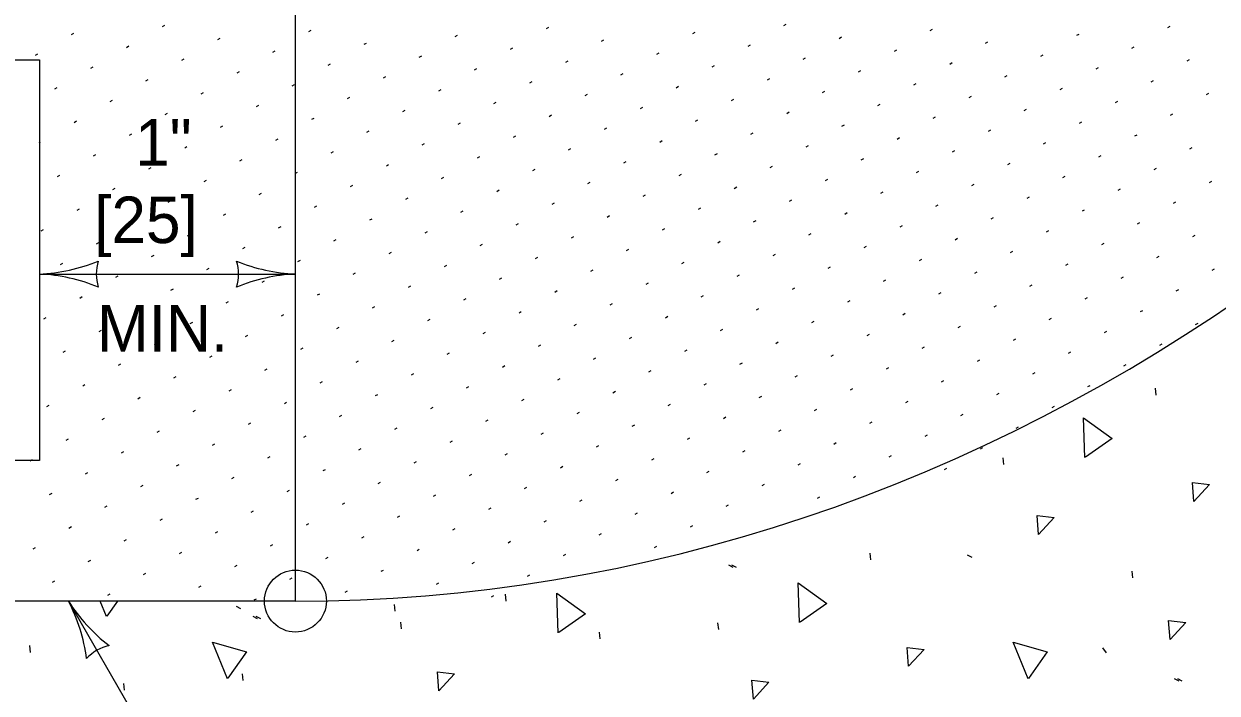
# Model space of a CAD drawing. Extents: x 49991.4 to 50021, y 49987.6 to 50011.4.
# Drawn here: x 50011.101 to 50012.641, y 49993.167 to 49994.031 of the extents above; entities that cross this region are included whole.
import ezdxf

# ---------------------------------------------------------------- set-up
doc = ezdxf.new("R2010")
doc.units = 0
for name, color, linetype in [('Level 1', 7, 'Continuous'), ('Level 15', 7, 'Continuous'), ('Level 2', 7, 'Continuous'), ('Level 3', 7, 'Continuous'), ('Level 4', 7, 'Continuous')]:
    doc.layers.add(name, color=color, linetype=linetype)

msp = doc.modelspace()

# ---------------------------------------------------------------- linework, layer by layer
at = {"layer": 'Level 1'}
for p, q in [((50010.6323, 49993.984), (50011.1207, 49993.984)), ((50011.1207, 49993.984), (50011.1207, 49993.4673)), ((50011.1207, 49993.4673), (50010.6333, 49993.4673)), ((50011.4513, 49993.2857), (50004.6259, 49993.2857))]:
    msp.add_line(p, q, dxfattribs=at)
msp.add_ellipse((50011.4513, 49996.2377), major_axis=(0, -2.952), ratio=0.83118, start_param=0, end_param=1.074783, dxfattribs=at)
at = {"layer": 'Level 15'}
msp.add_circle((50011.4513, 49993.2857), 0.04, dxfattribs=at)
at = {"layer": 'Level 3'}
for p, q in [((50011.4514, 49993.2857), (50011.4512, 49994.8936)), ((50011.2796, 49994.0271), (50011.2827, 49994.0288)), ((50011.7753, 49994.0246), (50011.7784, 49994.0264)), ((50012.082, 49994.0285), (50012.0851, 49994.0302)), ((50012.5777, 49994.026), (50012.5808, 49994.0277)), ((50011.162, 49994.0169), (50011.165, 49994.0186)), ((50011.351, 49994.0105), (50011.354, 49994.0123)), ((50011.4687, 49994.0207), (50011.4717, 49994.0225)), ((50011.6577, 49994.0144), (50011.6607, 49994.0161)), ((50011.8467, 49994.0081), (50011.8497, 49994.0098)), ((50011.9644, 49994.0183), (50011.9674, 49994.02)), ((50012.1534, 49994.0119), (50012.1564, 49994.0137)), ((50012.2711, 49994.0221), (50012.2741, 49994.0239)), ((50012.4601, 49994.0158), (50012.4631, 49994.0175)), ((50011.2333, 49994.0003), (50011.2363, 49994.0021)), ((50011.4223, 49993.994), (50011.4253, 49993.9957)), ((50011.54, 49994.0042), (50011.543, 49994.0059)), ((50011.729, 49993.9978), (50011.732, 49993.9996)), ((50012.0357, 49994.0017), (50012.0387, 49994.0035)), ((50012.2247, 49993.9954), (50012.2277, 49993.9971)), ((50012.3424, 49994.0056), (50012.3454, 49994.0073)), ((50012.5314, 49993.9992), (50012.5344, 49994.001)), ((50011.1156, 49993.9901), (50011.1187, 49993.9919)), ((50011.3046, 49993.9838), (50011.3077, 49993.9855)), ((50011.4937, 49993.9774), (50011.4967, 49993.9792)), ((50011.6113, 49993.9876), (50011.6144, 49993.9894)), ((50011.8003, 49993.9813), (50011.8034, 49993.983)), ((50011.918, 49993.9915), (50011.9211, 49993.9933)), ((50012.107, 49993.9852), (50012.1101, 49993.9869)), ((50012.2961, 49993.9788), (50012.2991, 49993.9806)), ((50012.4137, 49993.989), (50012.4168, 49993.9908)), ((50012.6027, 49993.9827), (50012.6058, 49993.9844)), ((50011.187, 49993.9736), (50011.19, 49993.9753)), ((50011.376, 49993.9672), (50011.379, 49993.969)), ((50011.565, 49993.9609), (50011.568, 49993.9626)), ((50011.6827, 49993.9711), (50011.6857, 49993.9728)), ((50011.8717, 49993.9648), (50011.8747, 49993.9665)), ((50011.9894, 49993.975), (50011.9924, 49993.9767)), ((50012.1784, 49993.9686), (50012.1814, 49993.9704)), ((50012.3674, 49993.9623), (50012.3704, 49993.964)), ((50012.4851, 49993.9725), (50012.4881, 49993.9742)), ((50011.1406, 49993.9468), (50011.1437, 49993.9486)), ((50011.2583, 49993.957), (50011.2613, 49993.9588)), ((50011.4473, 49993.9507), (50011.4503, 49993.9524)), ((50011.754, 49993.9545), (50011.757, 49993.9563)), ((50011.943, 49993.9482), (50011.9461, 49993.95)), ((50012.0607, 49993.9584), (50012.0637, 49993.9602)), ((50012.2497, 49993.9521), (50012.2527, 49993.9538)), ((50012.4387, 49993.9457), (50012.4418, 49993.9475)), ((50012.5564, 49993.9559), (50012.5594, 49993.9577)), ((50011.212, 49993.9303), (50011.215, 49993.932)), ((50011.3296, 49993.9405), (50011.3327, 49993.9422)), ((50011.5187, 49993.9341), (50011.5217, 49993.9359)), ((50011.6363, 49993.9443), (50011.6394, 49993.9461)), ((50011.8253, 49993.938), (50011.8284, 49993.9397)), ((50012.0144, 49993.9317), (50012.0174, 49993.9334)), ((50012.132, 49993.9419), (50012.1351, 49993.9436)), ((50012.3211, 49993.9355), (50012.3241, 49993.9373)), ((50012.6277, 49993.9394), (50012.6308, 49993.9411)), ((50011.401, 49993.9239), (50011.404, 49993.9257)), ((50011.59, 49993.9176), (50011.593, 49993.9193)), ((50011.7077, 49993.9278), (50011.7107, 49993.9295)), ((50011.8967, 49993.9215), (50011.8997, 49993.9232)), ((50012.0857, 49993.9151), (50012.0887, 49993.9169)), ((50012.2034, 49993.9253), (50012.2064, 49993.9271)), ((50012.3924, 49993.919), (50012.3954, 49993.9207)), ((50012.5101, 49993.9292), (50012.5131, 49993.9309)), ((50011.1656, 49993.9035), (50011.1687, 49993.9053)), ((50011.2833, 49993.9137), (50011.2863, 49993.9155)), ((50011.4723, 49993.9074), (50011.4753, 49993.9091)), ((50011.6613, 49993.901), (50011.6644, 49993.9028)), ((50011.779, 49993.9112), (50011.782, 49993.913)), ((50011.968, 49993.9049), (50011.9711, 49993.9067)), ((50012.2747, 49993.9088), (50012.2777, 49993.9105)), ((50012.4637, 49993.9024), (50012.4668, 49993.9042)), ((50012.5814, 49993.9126), (50012.5844, 49993.9144)), ((50011.237, 49993.887), (50011.24, 49993.8887)), ((50011.3546, 49993.8972), (50011.3577, 49993.8989)), ((50011.5437, 49993.8908), (50011.5467, 49993.8926)), ((50011.7327, 49993.8845), (50011.7357, 49993.8862)), ((50011.8503, 49993.8947), (50011.8534, 49993.8964)), ((50012.0394, 49993.8884), (50012.0424, 49993.8901)), ((50012.157, 49993.8986), (50012.1601, 49993.9003)), ((50012.3461, 49993.8922), (50012.3491, 49993.894)), ((50012.5351, 49993.8859), (50012.5381, 49993.8876)), ((50011.1205, 49993.8775), (50011.1223, 49993.8785)), ((50011.3083, 49993.8704), (50011.3113, 49993.8722)), ((50011.426, 49993.8806), (50011.429, 49993.8824)), ((50011.615, 49993.8743), (50011.618, 49993.876)), ((50011.9217, 49993.8781), (50011.9247, 49993.8799)), ((50012.1107, 49993.8718), (50012.1137, 49993.8736)), ((50012.2284, 49993.882), (50012.2314, 49993.8838)), ((50012.4174, 49993.8757), (50012.4204, 49993.8774)), ((50012.6064, 49993.8693), (50012.6094, 49993.8711)), ((50011.1906, 49993.8602), (50011.1937, 49993.862)), ((50011.3796, 49993.8539), (50011.3827, 49993.8556)), ((50011.4973, 49993.8641), (50011.5003, 49993.8658)), ((50011.6863, 49993.8577), (50011.6894, 49993.8595)), ((50011.804, 49993.8679), (50011.807, 49993.8697)), ((50011.993, 49993.8616), (50011.9961, 49993.8634)), ((50012.182, 49993.8553), (50012.1851, 49993.857)), ((50012.2997, 49993.8655), (50012.3027, 49993.8672)), ((50012.4887, 49993.8591), (50012.4918, 49993.8609)), ((50011.262, 49993.8437), (50011.265, 49993.8454)), ((50011.5687, 49993.8475), (50011.5717, 49993.8493)), ((50011.7577, 49993.8412), (50011.7607, 49993.8429)), ((50011.8753, 49993.8514), (50011.8784, 49993.8531)), ((50012.0644, 49993.8451), (50012.0674, 49993.8468)), ((50012.2534, 49993.8387), (50012.2564, 49993.8405)), ((50012.3711, 49993.8489), (50012.3741, 49993.8507)), ((50012.5601, 49993.8426), (50012.5631, 49993.8443)), ((50011.1443, 49993.8335), (50011.1473, 49993.8352)), ((50011.3333, 49993.8271), (50011.3363, 49993.8289)), ((50011.451, 49993.8373), (50011.454, 49993.8391)), ((50011.64, 49993.831), (50011.643, 49993.8327)), ((50011.829, 49993.8246), (50011.832, 49993.8264)), ((50011.9467, 49993.8348), (50011.9497, 49993.8366)), ((50012.1357, 49993.8285), (50012.1387, 49993.8303)), ((50012.3247, 49993.8222), (50012.3277, 49993.8239)), ((50012.4424, 49993.8324), (50012.4454, 49993.8341)), ((50012.6314, 49993.826), (50012.6344, 49993.8278)), ((50011.2156, 49993.8169), (50011.2187, 49993.8187)), ((50011.4046, 49993.8106), (50011.4077, 49993.8123)), ((50011.5223, 49993.8208), (50011.5253, 49993.8225)), ((50011.7113, 49993.8144), (50011.7144, 49993.8162)), ((50011.9003, 49993.8081), (50011.9034, 49993.8098)), ((50012.018, 49993.8183), (50012.0211, 49993.8201)), ((50012.207, 49993.812), (50012.2101, 49993.8137)), ((50012.5137, 49993.8158), (50012.5168, 49993.8176)), ((50011.287, 49993.8004), (50011.29, 49993.8021)), ((50011.476, 49993.794), (50011.479, 49993.7958)), ((50011.5937, 49993.8042), (50011.5967, 49993.806)), ((50011.7827, 49993.7979), (50011.7857, 49993.7996)), ((50011.9717, 49993.7915), (50011.9747, 49993.7933)), ((50012.0894, 49993.8018), (50012.0924, 49993.8035)), ((50012.2784, 49993.7954), (50012.2814, 49993.7972)), ((50012.3961, 49993.8056), (50012.3991, 49993.8074)), ((50012.5851, 49993.7993), (50012.5881, 49993.801)), ((50011.1693, 49993.7902), (50011.1723, 49993.7919)), ((50011.3583, 49993.7838), (50011.3613, 49993.7856)), ((50011.5473, 49993.7775), (50011.5503, 49993.7792)), ((50011.665, 49993.7877), (50011.668, 49993.7894)), ((50011.854, 49993.7813), (50011.857, 49993.7831)), ((50012.1607, 49993.7852), (50012.1637, 49993.787)), ((50012.3497, 49993.7789), (50012.3527, 49993.7806)), ((50012.4674, 49993.7891), (50012.4704, 49993.7908)), ((50011.1229, 49993.7634), (50011.126, 49993.7652)), ((50011.2406, 49993.7736), (50011.2437, 49993.7754)), ((50011.4296, 49993.7673), (50011.4327, 49993.769)), ((50011.6187, 49993.7609), (50011.6217, 49993.7627)), ((50011.7363, 49993.7711), (50011.7394, 49993.7729)), ((50011.9253, 49993.7648), (50011.9284, 49993.7665)), ((50012.043, 49993.775), (50012.0461, 49993.7767)), ((50012.232, 49993.7687), (50012.2351, 49993.7704)), ((50012.4211, 49993.7623), (50012.4241, 49993.7641)), ((50012.5387, 49993.7725), (50012.5418, 49993.7743)), ((50011.1943, 49993.7469), (50011.1973, 49993.7486)), ((50011.312, 49993.7571), (50011.315, 49993.7588)), ((50011.501, 49993.7507), (50011.504, 49993.7525)), ((50011.8077, 49993.7546), (50011.8107, 49993.7563)), ((50011.9967, 49993.7482), (50011.9997, 49993.75)), ((50012.1144, 49993.7585), (50012.1174, 49993.7602)), ((50012.3034, 49993.7521), (50012.3064, 49993.7539)), ((50012.4924, 49993.7458), (50012.4954, 49993.7475)), ((50012.6101, 49993.756), (50012.6131, 49993.7577)), ((50011.2656, 49993.7303), (50011.2687, 49993.7321)), ((50011.3833, 49993.7405), (50011.3863, 49993.7423)), ((50011.5723, 49993.7342), (50011.5753, 49993.7359)), ((50011.69, 49993.7444), (50011.693, 49993.7461)), ((50011.879, 49993.738), (50011.882, 49993.7398)), ((50012.068, 49993.7317), (50012.0711, 49993.7334)), ((50012.1857, 49993.7419), (50012.1887, 49993.7437)), ((50012.3747, 49993.7356), (50012.3777, 49993.7373)), ((50011.1479, 49993.7201), (50011.151, 49993.7219)), ((50011.4546, 49993.724), (50011.4577, 49993.7257)), ((50011.6437, 49993.7176), (50011.6467, 49993.7194)), ((50011.7613, 49993.7278), (50011.7644, 49993.7296)), ((50011.9503, 49993.7215), (50011.9534, 49993.7232)), ((50012.1394, 49993.7152), (50012.1424, 49993.7169)), ((50012.257, 49993.7254), (50012.2601, 49993.7271)), ((50012.4461, 49993.719), (50012.4491, 49993.7208)), ((50012.5637, 49993.7292), (50012.5668, 49993.731)), ((50011.2193, 49993.7036), (50011.2223, 49993.7053)), ((50011.337, 49993.7138), (50011.34, 49993.7155)), ((50011.526, 49993.7074), (50011.529, 49993.7092)), ((50011.715, 49993.7011), (50011.718, 49993.7028)), ((50011.8327, 49993.7113), (50011.8357, 49993.713)), ((50012.0217, 49993.7049), (50012.0247, 49993.7067)), ((50012.3284, 49993.7088), (50012.3314, 49993.7106)), ((50012.5174, 49993.7025), (50012.5204, 49993.7042)), ((50012.6351, 49993.7127), (50012.6381, 49993.7144)), ((50011.2906, 49993.687), (50011.2937, 49993.6888)), ((50011.4083, 49993.6972), (50011.4113, 49993.699)), ((50011.5973, 49993.6909), (50011.6003, 49993.6926)), ((50011.7863, 49993.6845), (50011.7894, 49993.6863)), ((50011.904, 49993.6947), (50011.907, 49993.6965)), ((50012.093, 49993.6884), (50012.0961, 49993.6901)), ((50012.2107, 49993.6986), (50012.2137, 49993.7004)), ((50012.3997, 49993.6923), (50012.4027, 49993.694)), ((50012.5887, 49993.6859), (50012.5918, 49993.6877)), ((50011.1729, 49993.6768), (50011.176, 49993.6786)), ((50011.362, 49993.6705), (50011.365, 49993.6722)), ((50011.4796, 49993.6807), (50011.4827, 49993.6824)), ((50011.6687, 49993.6743), (50011.6717, 49993.6761)), ((50011.8577, 49993.668), (50011.8607, 49993.6697)), ((50011.9753, 49993.6782), (50011.9784, 49993.6799)), ((50012.1644, 49993.6718), (50012.1674, 49993.6736)), ((50012.282, 49993.6821), (50012.2851, 49993.6838)), ((50012.4711, 49993.6757), (50012.4741, 49993.6775)), ((50011.2443, 49993.6603), (50011.2473, 49993.662)), ((50011.4333, 49993.6539), (50011.4363, 49993.6557)), ((50011.551, 49993.6641), (50011.554, 49993.6659)), ((50011.74, 49993.6578), (50011.743, 49993.6595)), ((50012.0467, 49993.6616), (50012.0497, 49993.6634)), ((50012.2357, 49993.6553), (50012.2387, 49993.6571)), ((50012.3534, 49993.6655), (50012.3564, 49993.6673)), ((50012.5424, 49993.6592), (50012.5454, 49993.6609)), ((50011.1266, 49993.6501), (50011.1296, 49993.6518)), ((50011.3156, 49993.6437), (50011.3187, 49993.6455)), ((50011.5046, 49993.6374), (50011.5077, 49993.6391)), ((50011.6223, 49993.6476), (50011.6253, 49993.6493)), ((50011.8113, 49993.6412), (50011.8144, 49993.643)), ((50011.929, 49993.6514), (50011.932, 49993.6532)), ((50012.118, 49993.6451), (50012.1211, 49993.6468)), ((50012.307, 49993.6388), (50012.3101, 49993.6405)), ((50012.4247, 49993.649), (50012.4277, 49993.6507)), ((50012.6137, 49993.6426), (50012.6168, 49993.6444)), ((50011.1979, 49993.6335), (50011.201, 49993.6353)), ((50011.387, 49993.6272), (50011.39, 49993.6289)), ((50011.6937, 49993.631), (50011.6967, 49993.6328)), ((50011.8827, 49993.6247), (50011.8857, 49993.6264)), ((50012.0003, 49993.6349), (50012.0034, 49993.6366)), ((50012.1894, 49993.6285), (50012.1924, 49993.6303)), ((50012.3784, 49993.6222), (50012.3814, 49993.624)), ((50012.4961, 49993.6324), (50012.4991, 49993.6342)), ((50011.1516, 49993.6068), (50011.1546, 49993.6085)), ((50011.2693, 49993.617), (50011.2723, 49993.6187)), ((50011.4583, 49993.6106), (50011.4613, 49993.6124)), ((50011.576, 49993.6208), (50011.579, 49993.6226)), ((50011.765, 49993.6145), (50011.768, 49993.6162)), ((50011.954, 49993.6081), (50011.957, 49993.6099)), ((50012.0717, 49993.6183), (50012.0747, 49993.6201)), ((50012.2607, 49993.612), (50012.2637, 49993.6137)), ((50012.5674, 49993.6159), (50012.5704, 49993.6176)), ((50011.3406, 49993.6004), (50011.3437, 49993.6022)), ((50011.5296, 49993.5941), (50011.5327, 49993.5958)), ((50011.6473, 49993.6043), (50011.6503, 49993.606)), ((50011.8363, 49993.5979), (50011.8394, 49993.5997)), ((50012.0253, 49993.5916), (50012.0284, 49993.5933)), ((50012.143, 49993.6018), (50012.1461, 49993.6035)), ((50012.332, 49993.5955), (50012.3351, 49993.5972)), ((50012.4497, 49993.6057), (50012.4527, 49993.6074)), ((50011.2229, 49993.5902), (50011.226, 49993.592)), ((50011.412, 49993.5839), (50011.415, 49993.5856)), ((50011.601, 49993.5775), (50011.604, 49993.5793)), ((50011.7187, 49993.5877), (50011.7217, 49993.5895)), ((50011.9077, 49993.5814), (50011.9107, 49993.5831)), ((50012.2144, 49993.5852), (50012.2174, 49993.587)), ((50012.4034, 49993.5789), (50012.4064, 49993.5807)), ((50012.5211, 49993.5891), (50012.5241, 49993.5909)), ((50011.1766, 49993.5634), (50011.1796, 49993.5652)), ((50011.2943, 49993.5737), (50011.2973, 49993.5754)), ((50011.4833, 49993.5673), (50011.4863, 49993.5691)), ((50011.6723, 49993.561), (50011.6753, 49993.5627)), ((50011.79, 49993.5712), (50011.793, 49993.5729)), ((50011.979, 49993.5648), (50011.982, 49993.5666)), ((50012.0967, 49993.575), (50012.0997, 49993.5768)), ((50012.2857, 49993.5687), (50012.2887, 49993.5704)), ((50012.4747, 49993.5624), (50012.4777, 49993.5641)), ((50011.2479, 49993.5469), (50011.251, 49993.5487)), ((50011.3656, 49993.5571), (50011.3687, 49993.5589)), ((50011.5546, 49993.5508), (50011.5577, 49993.5525)), ((50011.8613, 49993.5546), (50011.8644, 49993.5564)), ((50012.0503, 49993.5483), (50012.0534, 49993.55)), ((50012.168, 49993.5585), (50012.1711, 49993.5602)), ((50012.357, 49993.5522), (50012.3601, 49993.5539)), ((50011.1303, 49993.5367), (50011.1333, 49993.5384)), ((50011.3193, 49993.5304), (50011.3223, 49993.5321)), ((50011.437, 49993.5406), (50011.44, 49993.5423)), ((50011.626, 49993.5342), (50011.629, 49993.536)), ((50011.7437, 49993.5444), (50011.7467, 49993.5462)), ((50011.9327, 49993.5381), (50011.9357, 49993.5398)), ((50012.1217, 49993.5317), (50012.1247, 49993.5335)), ((50012.2394, 49993.5419), (50012.2424, 49993.5437)), ((50012.4284, 49993.5356), (50012.4314, 49993.5374)), ((50011.2016, 49993.5201), (50011.2046, 49993.5219)), ((50011.5083, 49993.524), (50011.5113, 49993.5258)), ((50011.6973, 49993.5177), (50011.7003, 49993.5194)), ((50011.815, 49993.5279), (50011.818, 49993.5296)), ((50012.004, 49993.5215), (50012.007, 49993.5233)), ((50012.193, 49993.5152), (50012.1961, 49993.5169)), ((50012.3107, 49993.5254), (50012.3137, 49993.5271)), ((50011.2729, 49993.5036), (50011.276, 49993.5054)), ((50011.3906, 49993.5138), (50011.3937, 49993.5156)), ((50011.5796, 49993.5075), (50011.5827, 49993.5092)), ((50011.7687, 49993.5011), (50011.7717, 49993.5029)), ((50011.8863, 49993.5113), (50011.8894, 49993.5131)), ((50012.0753, 49993.505), (50012.0784, 49993.5067)), ((50012.2644, 49993.4986), (50012.2674, 49993.5004)), ((50012.382, 49993.5088), (50012.3851, 49993.5106)), ((50011.1553, 49993.4934), (50011.1583, 49993.4951)), ((50011.3443, 49993.4871), (50011.3473, 49993.4888)), ((50011.462, 49993.4973), (50011.465, 49993.499)), ((50011.651, 49993.4909), (50011.654, 49993.4927)), ((50011.84, 49993.4846), (50011.843, 49993.4863)), ((50011.9577, 49993.4948), (50011.9607, 49993.4965)), ((50012.1467, 49993.4884), (50012.1497, 49993.4902)), ((50011.2266, 49993.4768), (50011.2296, 49993.4786)), ((50011.4156, 49993.4705), (50011.4187, 49993.4723)), ((50011.5333, 49993.4807), (50011.5363, 49993.4825)), ((50011.7223, 49993.4744), (50011.7253, 49993.4761)), ((50011.9113, 49993.468), (50011.9144, 49993.4698)), ((50012.029, 49993.4782), (50012.032, 49993.48)), ((50012.218, 49993.4719), (50012.2211, 49993.4736)), ((50012.3357, 49993.4821), (50012.3387, 49993.4838)), ((50011.1089, 49993.4666), (50011.112, 49993.4684)), ((50011.2979, 49993.4603), (50011.301, 49993.462)), ((50011.487, 49993.454), (50011.49, 49993.4557)), ((50011.6046, 49993.4642), (50011.6077, 49993.4659)), ((50011.7937, 49993.4578), (50011.7967, 49993.4596)), ((50012.1003, 49993.4617), (50012.1034, 49993.4634)), ((50012.2894, 49993.4553), (50012.2924, 49993.4571)), ((50011.1803, 49993.4501), (50011.1833, 49993.4518)), ((50011.3693, 49993.4438), (50011.3723, 49993.4455)), ((50011.5583, 49993.4374), (50011.5613, 49993.4392)), ((50011.676, 49993.4476), (50011.679, 49993.4494)), ((50011.865, 49993.4413), (50011.868, 49993.443)), ((50011.9827, 49993.4515), (50011.9857, 49993.4532)), ((50012.1717, 49993.4451), (50012.1747, 49993.4469)), ((50011.1339, 49993.4233), (50011.137, 49993.4251)), ((50011.2516, 49993.4335), (50011.2546, 49993.4353)), ((50011.4406, 49993.4272), (50011.4437, 49993.429)), ((50011.7473, 49993.4311), (50011.7503, 49993.4328)), ((50011.9363, 49993.4247), (50011.9394, 49993.4265)), ((50012.054, 49993.4349), (50012.057, 49993.4367)), ((50011.2053, 49993.4068), (50011.2083, 49993.4085)), ((50011.3229, 49993.417), (50011.326, 49993.4187)), ((50011.512, 49993.4107), (50011.515, 49993.4124)), ((50011.6296, 49993.4209), (50011.6327, 49993.4226)), ((50011.8187, 49993.4145), (50011.8217, 49993.4163)), ((50012.0077, 49993.4082), (50012.0107, 49993.4099)), ((50012.1253, 49993.4184), (50012.1284, 49993.4201)), ((50011.3943, 49993.4005), (50011.3973, 49993.4022)), ((50011.5833, 49993.3941), (50011.5863, 49993.3959)), ((50011.701, 49993.4043), (50011.704, 49993.4061)), ((50011.89, 49993.398), (50011.893, 49993.3997)), ((50011.1589, 49993.38), (50011.162, 49993.3818)), ((50011.2766, 49993.3902), (50011.2796, 49993.392)), ((50011.4656, 49993.3839), (50011.4687, 49993.3857)), ((50011.6546, 49993.3776), (50011.6577, 49993.3793)), ((50011.7723, 49993.3878), (50011.7753, 49993.3895)), ((50011.9613, 49993.3814), (50011.9644, 49993.3832)), ((50011.2303, 49993.3635), (50011.2333, 49993.3652)), ((50011.3479, 49993.3737), (50011.351, 49993.3754)), ((50011.537, 49993.3674), (50011.54, 49993.3691)), ((50011.726, 49993.361), (50011.729, 49993.3628)), ((50011.8437, 49993.3712), (50011.8467, 49993.373)), ((50011.1126, 49993.3533), (50011.1156, 49993.355)), ((50011.3016, 49993.3469), (50011.3046, 49993.3487)), ((50011.4193, 49993.3571), (50011.4223, 49993.3589)), ((50011.6083, 49993.3508), (50011.6113, 49993.3526)), ((50011.7973, 49993.3445), (50011.8003, 49993.3462)), ((50011.915, 49993.3547), (50011.918, 49993.3564)), ((50011.1839, 49993.3367), (50011.187, 49993.3385)), ((50011.3729, 49993.3304), (50011.376, 49993.3321)), ((50011.4906, 49993.3406), (50011.4937, 49993.3424)), ((50011.6796, 49993.3343), (50011.6827, 49993.336)), ((50011.2553, 49993.3202), (50011.2583, 49993.3219)), ((50011.4443, 49993.3138), (50011.4473, 49993.3156)), ((50011.562, 49993.3241), (50011.565, 49993.3258)), ((50011.751, 49993.3177), (50011.754, 49993.3195)), ((50011.1376, 49993.31), (50011.1406, 49993.3117)), ((50011.3266, 49993.3036), (50011.3296, 49993.3054)), ((50011.6333, 49993.3075), (50011.6363, 49993.3093)), ((50011.1581, 49993.2857), (50011.7617, 49992.2404)), ((50011.2089, 49993.2934), (50011.212, 49993.2952)), ((50011.3979, 49993.2871), (50011.401, 49993.2888)), ((50011.5156, 49993.2973), (50011.5187, 49993.2991)), ((50011.7046, 49993.291), (50011.7077, 49993.2927))]:
    msp.add_line(p, q, dxfattribs=at)
msp.add_lwpolyline([(50011.1207, 49993.7077), (50011.3394, 49993.7077), (50011.4513, 49993.7077)], dxfattribs=at)
for centre, radius, start, end in [((50011.1092, 49993.9404), 0.233, 272.8273, 292.0772), ((50011.2489, 49993.7077), 0.0548, 162.1388, 197.8612), ((50011.4605, 49993.9298), 0.2223, 247.456, 267.6395), ((50011.3231, 49993.7077), 0.0548, 342.1388, 17.8612), ((50011.1116, 49993.4855), 0.2223, 67.456, 87.6395), ((50011.4628, 49993.475), 0.233, 92.8273, 112.0772), ((50010.9612, 49993.1826), 0.2223, 7.456, 27.6395), ((50011.3539, 49993.412), 0.233, 212.8273, 232.0772), ((50011.2222, 49993.1747), 0.0548, 102.1388, 137.8612)]:
    msp.add_arc(centre, radius, start, end, dxfattribs=at)
at = {"layer": 'Level 4'}
for p, q in [((50012.5626, 49993.5516), (50012.5617, 49993.5603)), ((50012.3662, 49993.4618), (50012.3653, 49993.4705)), ((50012.1942, 49993.3389), (50012.1933, 49993.3476)), ((50012.0103, 49993.3323), (50012.0161, 49993.3295)), ((50012.0144, 49993.3323), (50012.0202, 49993.3295)), ((50012.3187, 49993.3452), (50012.3245, 49993.3423)), ((50012.5326, 49993.3158), (50012.5316, 49993.3245)), ((50011.7235, 49993.2857), (50011.7226, 49993.2944)), ((50011.3746, 49993.279), (50011.3803, 49993.2762)), ((50011.58, 49993.2727), (50011.5791, 49993.2814)), ((50011.3961, 49993.2662), (50011.4019, 49993.2633)), ((50011.4002, 49993.2662), (50011.406, 49993.2634)), ((50011.5884, 49993.2497), (50011.5875, 49993.2584)), ((50011.9979, 49993.2491), (50011.9969, 49993.2578)), ((50011.845, 49993.2369), (50011.844, 49993.2456)), ((50011.1093, 49993.2195), (50011.1084, 49993.2282)), ((50012.4933, 49993.2253), (50012.498, 49993.2189)), ((50011.2308, 49993.1707), (50011.2299, 49993.1794)), ((50011.3837, 49993.183), (50011.3828, 49993.1917)), ((50012.5861, 49993.1858), (50012.5919, 49993.1829)), ((50012.5902, 49993.1858), (50012.5959, 49993.1829))]:
    msp.add_line(p, q, dxfattribs=at)
for points in [[(50012.4707, 49993.4709), (50012.4689, 49993.5221), (50012.5059, 49993.4953), (50012.4715, 49993.4713)], [(50012.6114, 49993.4141), (50012.6095, 49993.4387), (50012.6315, 49993.436), (50012.6114, 49993.4141)], [(50012.411, 49993.3718), (50012.4092, 49993.3963), (50012.4312, 49993.3937), (50012.411, 49993.3718)], [(50012.1024, 49993.2582), (50012.1005, 49993.3094), (50012.1375, 49993.2826), (50012.1031, 49993.2586)], [(50011.2075, 49993.2656), (50011.1993, 49993.2857)], [(50011.2217, 49993.2857), (50011.208, 49993.2663)], [(50011.7907, 49993.2448), (50011.7888, 49993.296), (50011.8259, 49993.2692), (50011.7915, 49993.2452)], [(50012.5807, 49993.236), (50012.5788, 49993.2605), (50012.6009, 49993.2579), (50012.5807, 49993.236)], [(50011.3637, 49993.1853), (50011.3444, 49993.2328), (50011.3883, 49993.2202), (50011.3642, 49993.186)], [(50012.243, 49993.2015), (50012.2411, 49993.226), (50012.2631, 49993.2234), (50012.243, 49993.2015)], [(50012.3974, 49993.1852), (50012.3781, 49993.2326), (50012.4221, 49993.2201), (50012.398, 49993.1858)], [(50011.6365, 49993.1698), (50011.6347, 49993.1944), (50011.6567, 49993.1917), (50011.6365, 49993.1698)], [(50012.0426, 49993.1591), (50012.0408, 49993.1837), (50012.0628, 49993.181), (50012.0426, 49993.1591)]]:
    msp.add_lwpolyline(points, dxfattribs=at)

# ---------------------------------------------------------------- texts
at = {"layer": 'Level 2'}
for s, p in [('1"', (50011.2443, 49993.8477)), ('[25]', (50011.1914, 49993.7477)), ('MIN.', (50011.1951, 49993.6077))]:
    msp.add_text(s, height=0.06, dxfattribs=at).set_placement(p)

doc.saveas('drawing.dxf')
